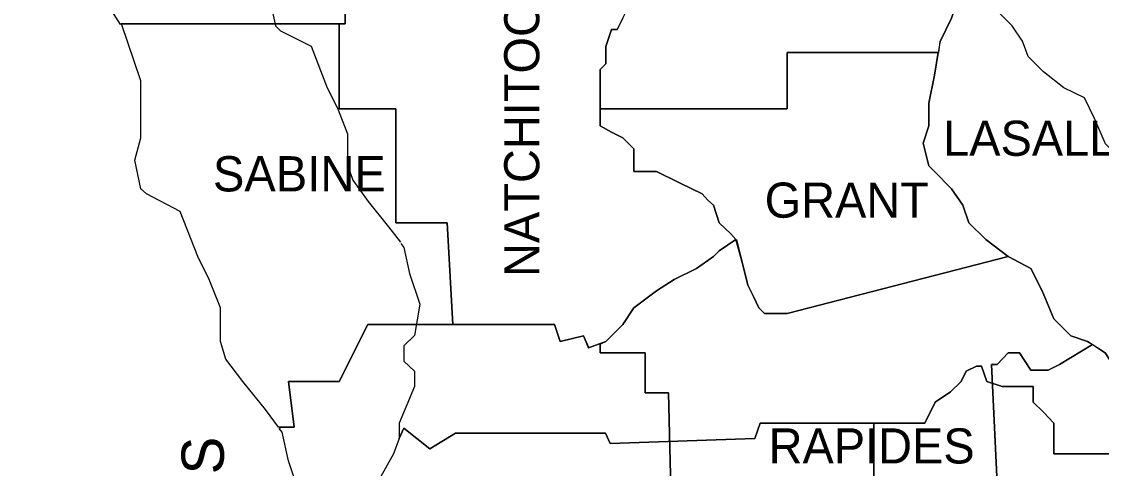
# Model space of a CAD drawing. Extents: x 0.19 to 2.82, y 0.04 to 1.79.
# Drawn here: x 2.194 to 2.3524, y 1.5609 to 1.6264 of the extents above; entities that cross this region are included whole.
import ezdxf

# ---------------------------------------------------------------- set-up
doc = ezdxf.new("R2010")
doc.units = 0
for name, color, linetype in [('Dist03', 7, 'Continuous'), ('Dist07', 7, 'Continuous'), ('Dist08', 7, 'Continuous'), ('Dist58', 7, 'Continuous'), ('Standard Info', 7, 'Continuous')]:
    doc.layers.add(name, color=color, linetype=linetype)

msp = doc.modelspace()

# ---------------------------------------------------------------- linework, layer by layer
at = {"layer": 'Dist03'}
for points in [[(2.3469, 1.56308), (2.3454, 1.56308), (2.3454, 1.56758), (2.3439, 1.56917), (2.3424, 1.57067), (2.3424, 1.57292), (2.34015, 1.57292), (2.33782, 1.57292), (2.33557, 1.57367), (2.33482, 1.57592), (2.33407, 1.57592), (2.33257, 1.57517), (2.33182, 1.57367), (2.33024, 1.57217), (2.32799, 1.57067), (2.32649, 1.56758), (2.31899, 1.56758)], [(2.31899, 1.56758), (2.31899, 1.54042), (2.31965, 1.53958), (2.31899, 1.53733), (2.3174, 1.53508), (2.31815, 1.53283), (2.3174, 1.53058)], [(2.37715, 1.56308), (2.3469, 1.56308)]]:
    msp.add_lwpolyline(points, dxfattribs=at)
at = {"layer": 'Dist07'}
for points in [[(2.30232, 1.56758), (2.30157, 1.56533), (2.28032, 1.56458), (2.27965, 1.56608), (2.25765, 1.56608), (2.2539, 1.56383), (2.25007, 1.56683), (2.2494, 1.56533)], [(2.31899, 1.56758), (2.30232, 1.56758)], [(2.3174, 1.53058), (2.31815, 1.53283), (2.3174, 1.53508), (2.31899, 1.53733), (2.31965, 1.53958), (2.31899, 1.54042), (2.31899, 1.56758)], [(2.2494, 1.56533), (2.24857, 1.56308)], [(2.24857, 1.56308), (2.24182, 1.551), (2.23799, 1.54267), (2.23882, 1.54042), (2.23949, 1.53583), (2.23882, 1.53208), (2.23799, 1.53058), (2.23649, 1.5275), (2.23649, 1.52742)]]:
    msp.add_lwpolyline(points, dxfattribs=at)
at = {"layer": 'Dist08'}
for points in [[(2.22865, 1.64775), (2.23124, 1.64025), (2.23124, 1.63267), (2.2304, 1.62967), (2.23124, 1.62583), (2.23199, 1.62508), (2.23649, 1.62283), (2.23882, 1.61675), (2.24032, 1.61375), (2.24182, 1.61), (2.24182, 1.60542), (2.24257, 1.60317), (2.24482, 1.60008), (2.24782, 1.59633), (2.24957, 1.59408)], [(2.36207, 1.60008), (2.36132, 1.60167), (2.35982, 1.60392), (2.35749, 1.60542), (2.35524, 1.60617), (2.35299, 1.6085), (2.3514, 1.61225), (2.3499, 1.61525), (2.3469, 1.61675), (2.3439, 1.61908), (2.34165, 1.62133), (2.34082, 1.62358), (2.33932, 1.62583), (2.33707, 1.62808), (2.33632, 1.62883), (2.33557, 1.63192), (2.33632, 1.63417), (2.33632, 1.63717), (2.33707, 1.64092), (2.33757, 1.644)], [(2.24965, 1.59392), (2.25007, 1.59333), (2.2509, 1.5895), (2.2524, 1.585), (2.25165, 1.58042), (2.25007, 1.57892), (2.25007, 1.57667), (2.25165, 1.57517), (2.25165, 1.57292), (2.2494, 1.56758), (2.2494, 1.56533)], [(2.30232, 1.56758), (2.32649, 1.56758), (2.32799, 1.57067), (2.33024, 1.57217), (2.33182, 1.57367), (2.33257, 1.57517), (2.33407, 1.57592), (2.33482, 1.57592), (2.33557, 1.57367), (2.33782, 1.57292), (2.34015, 1.57292), (2.3424, 1.57292)], [(2.3424, 1.57292), (2.3424, 1.57067), (2.3439, 1.56917), (2.3454, 1.56758), (2.3454, 1.56308), (2.3764, 1.56308)], [(2.2494, 1.56533), (2.25007, 1.56683), (2.2539, 1.56383), (2.25765, 1.56608), (2.27965, 1.56608), (2.28032, 1.56458), (2.30157, 1.56533), (2.30232, 1.56758)]]:
    msp.add_lwpolyline(points, dxfattribs=at)
at = {"layer": 'Dist58'}
msp.add_lwpolyline([(2.36207, 1.60008), (2.36132, 1.60167), (2.35982, 1.60392), (2.35749, 1.60542), (2.35524, 1.60617), (2.35299, 1.6085), (2.3514, 1.61225), (2.3499, 1.61525), (2.3469, 1.61675), (2.3439, 1.61908), (2.34165, 1.62133), (2.34082, 1.62358), (2.33932, 1.62583), (2.33707, 1.62808), (2.33632, 1.62883), (2.33557, 1.63192), (2.33632, 1.63417), (2.33632, 1.63717), (2.33707, 1.64092), (2.33757, 1.644)], dxfattribs=at)
at = {"layer": 'Standard Info'}
for p, q in [((2.20866, 1.62611), (2.20848, 1.62601)), ((2.32865, 1.62308), (2.32847, 1.62189)), ((2.27714, 1.57862), (2.27888, 1.57926)), ((2.27888, 1.57926), (2.27906, 1.57926)), ((2.23204, 1.56698), (2.23167, 1.56698)), ((2.23176, 1.5668), (2.23204, 1.56698))]:
    msp.add_line(p, q, dxfattribs=at)
for points in [[(2.24056, 1.62611), (2.24148, 1.62611), (2.24148, 1.63188), (2.24313, 1.63353), (2.24386, 1.63353), (2.2456, 1.6328), (2.24643, 1.63353), (2.2489, 1.63353), (2.24973, 1.63188), (2.25312, 1.63106), (2.2556, 1.63106), (2.25725, 1.63188), (2.25807, 1.6328), (2.25807, 1.63775), (2.2655, 1.63857), (2.26385, 1.64105), (2.26385, 1.6427), (2.2655, 1.64444), (2.26476, 1.64691), (2.26302, 1.64856), (2.26302, 1.65021), (2.2622, 1.65186), (2.26137, 1.65351)], [(2.27888, 1.61364), (2.27888, 1.61941), (2.2797, 1.62024), (2.2797, 1.62106), (2.2797, 1.62281), (2.28053, 1.62528), (2.28135, 1.62528), (2.28218, 1.62693), (2.283, 1.62858), (2.28383, 1.63106), (2.28548, 1.6328), (2.28465, 1.63692), (2.28465, 1.64105), (2.28465, 1.64352), (2.28465, 1.64609), (2.28383, 1.64856), (2.28218, 1.65104), (2.28099, 1.65351)], [(2.33131, 1.65351), (2.33131, 1.62941), (2.3304, 1.62693), (2.32875, 1.62354), (2.32865, 1.62308)], [(2.20848, 1.62601), (2.20316, 1.63445), (2.19647, 1.6427), (2.194, 1.64444)], [(2.24643, 1.63353), (2.2456, 1.6328), (2.24386, 1.63353), (2.24313, 1.63353), (2.24148, 1.63188), (2.24148, 1.62611), (2.24056, 1.62611)], [(2.32856, 1.62189), (2.32875, 1.62354), (2.3304, 1.62693), (2.33131, 1.62941), (2.33131, 1.63353)], [(2.28218, 1.62693), (2.28135, 1.62528), (2.28053, 1.62528), (2.2797, 1.62281), (2.2797, 1.62106), (2.2797, 1.62024), (2.27888, 1.61941), (2.27888, 1.61116), (2.28053, 1.61025), (2.28218, 1.60942), (2.28383, 1.60777), (2.28383, 1.60695), (2.28383, 1.60447), (2.28713, 1.60447), (2.29052, 1.60282), (2.29382, 1.60117), (2.29465, 1.60026), (2.29547, 1.59952), (2.2963, 1.59696), (2.29804, 1.59531), (2.29877, 1.59448)], [(2.24056, 1.62611), (2.20866, 1.62611)], [(2.23167, 1.56698), (2.22975, 1.56955), (2.22645, 1.57367), (2.22397, 1.57697), (2.22315, 1.57954), (2.22315, 1.58449), (2.2215, 1.58861), (2.21985, 1.59201), (2.21728, 1.59861), (2.21233, 1.60117), (2.2115, 1.60191), (2.21059, 1.60612), (2.2115, 1.60942), (2.2115, 1.61776), (2.20866, 1.62611)], [(2.20866, 1.62611), (2.24056, 1.62611)], [(2.24056, 1.62611), (2.24056, 1.61364), (2.2489, 1.61364), (2.2489, 1.59696), (2.25642, 1.59696), (2.25725, 1.58201)], [(2.25725, 1.58201), (2.25642, 1.59696), (2.2489, 1.59696), (2.2489, 1.61364), (2.24056, 1.61364), (2.24056, 1.62611)], [(2.32847, 1.62189), (2.30629, 1.62189), (2.30629, 1.61364), (2.28383, 1.61364), (2.27888, 1.61364)], [(2.27888, 1.61364), (2.28383, 1.61364), (2.30629, 1.61364), (2.30629, 1.62189), (2.32847, 1.62189)], [(2.35542, 1.57367), (2.3546, 1.57532), (2.35295, 1.57789), (2.35038, 1.57954), (2.3479, 1.58036), (2.34543, 1.58284), (2.34369, 1.58696), (2.34204, 1.59026), (2.33874, 1.59201), (2.33544, 1.59448), (2.33296, 1.59696), (2.33205, 1.59952), (2.3304, 1.60191), (2.32792, 1.60447), (2.3271, 1.6053), (2.32627, 1.6086), (2.3271, 1.61116), (2.3271, 1.61446), (2.32792, 1.61859), (2.32847, 1.62189)], [(2.32847, 1.62189), (2.32792, 1.61859), (2.3271, 1.61446), (2.3271, 1.61116), (2.32627, 1.6086), (2.3271, 1.6053), (2.32792, 1.60447), (2.3304, 1.60191), (2.33205, 1.59952), (2.33296, 1.59696), (2.33544, 1.59448), (2.33874, 1.59201)], [(2.33874, 1.59201), (2.30629, 1.58366), (2.30299, 1.58366), (2.30216, 1.58449), (2.30134, 1.58614), (2.30051, 1.58779), (2.29969, 1.59118), (2.29877, 1.59448), (2.29804, 1.59531), (2.2963, 1.59696), (2.29547, 1.59952), (2.29465, 1.60026), (2.29382, 1.60117), (2.29052, 1.60282), (2.28713, 1.60447), (2.28383, 1.60447), (2.28383, 1.60695), (2.28383, 1.60777), (2.28218, 1.60942), (2.28053, 1.61025), (2.27888, 1.61116), (2.27888, 1.61364)], [(2.29877, 1.59448), (2.2963, 1.59283), (2.29547, 1.59201), (2.293, 1.59026), (2.2897, 1.58861), (2.28713, 1.58696), (2.28383, 1.58449), (2.28218, 1.58201), (2.2797, 1.57954), (2.27714, 1.57862)], [(2.27714, 1.57862), (2.2797, 1.57954), (2.28218, 1.58201), (2.28383, 1.58449), (2.28713, 1.58696), (2.2897, 1.58861), (2.293, 1.59026), (2.29547, 1.59201), (2.2963, 1.59283), (2.29877, 1.59448)], [(2.27906, 1.57926), (2.2797, 1.57954), (2.28218, 1.58201), (2.28383, 1.58449), (2.28713, 1.58696), (2.2897, 1.58861), (2.293, 1.59026), (2.29547, 1.59201), (2.2963, 1.59283), (2.29877, 1.59448)], [(2.29886, 1.59448), (2.29969, 1.59118), (2.30051, 1.58779), (2.30134, 1.58614), (2.30216, 1.58449), (2.30299, 1.58366), (2.30629, 1.58366), (2.33874, 1.59201)], [(2.33874, 1.59201), (2.34204, 1.59026), (2.34369, 1.58696), (2.34543, 1.58284), (2.3479, 1.58036), (2.35038, 1.57954), (2.35111, 1.57908)], [(2.25725, 1.58201), (2.24478, 1.58201), (2.24056, 1.57367), (2.23314, 1.57367), (2.23396, 1.56698), (2.23204, 1.56698)], [(2.23204, 1.56698), (2.23396, 1.56698), (2.23314, 1.57367), (2.24056, 1.57367), (2.24478, 1.58201), (2.27219, 1.58201), (2.27301, 1.57954), (2.2764, 1.58036), (2.27714, 1.57862)], [(2.23204, 1.56698), (2.23396, 1.56698), (2.23314, 1.57367), (2.24056, 1.57367), (2.24478, 1.58201), (2.27219, 1.58201), (2.27301, 1.57954), (2.2764, 1.58036), (2.27714, 1.57871)], [(2.27714, 1.57862), (2.2764, 1.58036), (2.27301, 1.57954), (2.27219, 1.58201), (2.25725, 1.58201)], [(2.27888, 1.57926), (2.27888, 1.57789), (2.28548, 1.57789), (2.28548, 1.57202), (2.28887, 1.57202), (2.2897, 1.53792)], [(2.27888, 1.57926), (2.27888, 1.57789), (2.28548, 1.57789), (2.28548, 1.57202), (2.28887, 1.57202), (2.2897, 1.53792)], [(2.2897, 1.53792), (2.28887, 1.57202), (2.28548, 1.57202), (2.28548, 1.57789), (2.27888, 1.57789), (2.27888, 1.57926)], [(2.27888, 1.57917), (2.27888, 1.57789), (2.28548, 1.57789), (2.28548, 1.57202), (2.28887, 1.57202), (2.2897, 1.53792)], [(2.35111, 1.57908), (2.34625, 1.57615), (2.3446, 1.57532), (2.34295, 1.57532), (2.34204, 1.57532), (2.34039, 1.57789), (2.33874, 1.57789), (2.33709, 1.57615), (2.33626, 1.57615), (2.33709, 1.55873), (2.33791, 1.55121), (2.34039, 1.5437), (2.33379, 1.5437)], [(2.33379, 1.5437), (2.34039, 1.5437), (2.33791, 1.55121), (2.33709, 1.55873), (2.33626, 1.57615), (2.33709, 1.57615), (2.33874, 1.57789), (2.34039, 1.57789), (2.34204, 1.57532), (2.34295, 1.57532), (2.3446, 1.57532), (2.34625, 1.57615), (2.35111, 1.57908)], [(2.35111, 1.57908), (2.35295, 1.57789), (2.3546, 1.57532), (2.35542, 1.57367), (2.35707, 1.57202), (2.3579, 1.57037), (2.35955, 1.56955), (2.3612, 1.5712), (2.36037, 1.57285), (2.36202, 1.5745), (2.36624, 1.5745), (2.36871, 1.5712), (2.37119, 1.56863), (2.37531, 1.56698), (2.37788, 1.56698), (2.37953, 1.56625), (2.38118, 1.56451), (2.38035, 1.56203), (2.37953, 1.55873), (2.37953, 1.55534), (2.37788, 1.55369), (2.37586, 1.54975)], [(2.23149, 1.53536), (2.23149, 1.53792), (2.23396, 1.5437), (2.23396, 1.54626), (2.23222, 1.54791), (2.23222, 1.55039), (2.23396, 1.55204), (2.23479, 1.55699), (2.23314, 1.56203), (2.23222, 1.56625), (2.23176, 1.5668)]]:
    msp.add_lwpolyline(points, dxfattribs=at)

# ---------------------------------------------------------------- texts
for s, height, p in [('NATCHITOCHES', 0.0051469, (2.26994, 1.589)), ('T E X A S', 0.0062, (2.22366, 1.52919))]:
    msp.add_text(s, height=height, rotation=90, dxfattribs=at).set_placement(p)
for s, height, p in [('LASALLE', 0.005147, (2.32918, 1.60676)), ('SABINE', 0.00517, (2.22206, 1.60154)), ('GRANT', 0.005147, (2.303, 1.59769)), ('RAPIDES', 0.005147, (2.30358, 1.56166))]:
    msp.add_text(s, height=height, dxfattribs=at).set_placement(p)

doc.saveas('drawing.dxf')
